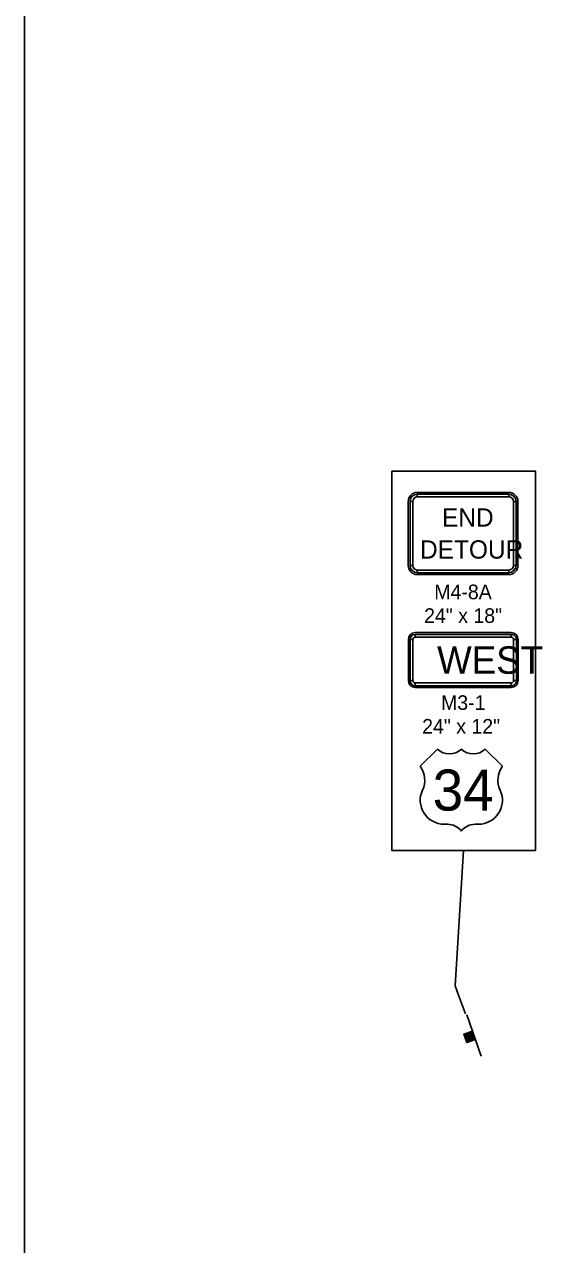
# Model space of a CAD drawing. Extents: x 10133 to 81668, y 6132 to 11018.
# Drawn here: x 10133 to 10418, y 8934 to 9603 of the extents above; entities that cross this region are included whole.
import ezdxf

# ---------------------------------------------------------------- set-up
doc = ezdxf.new("R2010")
doc.units = 0
for name, color, linetype in [('dsnTextFinalPlan', 7, 'Continuous'), ('Level 10', 7, 'Continuous'), ('Level 4', 7, 'Continuous'), ('Level 5', 7, 'Continuous'), ('SheetBorder', 7, 'Continuous'), ('SheetText', 7, 'Continuous')]:
    doc.layers.add(name, color=color, linetype=linetype)

msp = doc.modelspace()

# ---------------------------------------------------------------- linework, layer by layer
at = {"layer": 'dsnTextFinalPlan'}
for p, q in [((10374.94, 9060.01), (10382.82, 9037.34)), ((10373.66, 9049.53), (10375.26, 9044.93)), ((10375.52, 9045.02), (10373.92, 9049.62)), ((10374.11, 9049.69), (10375.71, 9045.08)), ((10375.97, 9045.17), (10374.37, 9049.78)), ((10374.56, 9049.84), (10376.14, 9045.23)), ((10376.5, 9045.36), (10374.91, 9049.97)), ((10375.08, 9050.03), (10376.68, 9045.42)), ((10377.04, 9045.54), (10375.44, 9050.15)), ((10375.75, 9050.26), (10377.35, 9045.65)), ((10377.61, 9045.74), (10376.02, 9050.35)), ((10376.19, 9050.41), (10377.8, 9045.81)), ((10378.01, 9045.88), (10376.41, 9050.49)), ((10376.69, 9050.58), (10378.29, 9045.98)), ((10378.46, 9046.04), (10376.86, 9050.64)), ((10377.04, 9050.71), (10378.65, 9046.1)), ((10378.86, 9046.18), (10377.26, 9050.78)), ((10377.48, 9050.86), (10379.08, 9046.25)), ((10379.31, 9046.33), (10377.71, 9050.94))]:
    msp.add_line(p, q, dxfattribs=at)
for points in [[(10333.75, 9358.04), (10412.57, 9358.04), (10412.57, 9150.14), (10333.75, 9150.14)], [(10333.75, 9358.04), (10412.57, 9358.04), (10412.57, 9150.14), (10333.75, 9150.14)], [(10379.57, 9046.42), (10377.96, 9051.06), (10373.32, 9049.45), (10374.94, 9044.81)]]:
    msp.add_lwpolyline(points, close=True, dxfattribs=at)
msp.add_lwpolyline([(10374.15, 9060.58), (10370.43, 9070.84), (10368.58, 9075.97), (10373.16, 9150.14)], dxfattribs=at)
at = {"layer": 'Level 10'}
for p, q in [((10342.78, 9341.49), (10342.78, 9306.42)), ((10343.78, 9341.49), (10343.78, 9306.42)), ((10345.29, 9341.49), (10343.78, 9341.49)), ((10343.78, 9341.49), (10345.29, 9341.49)), ((10345.29, 9306.42), (10345.29, 9341.49)), ((10397.9, 9346.5), (10347.79, 9346.5)), ((10347.79, 9344), (10347.79, 9345.5)), ((10397.9, 9345.5), (10347.79, 9345.5)), ((10347.79, 9345.5), (10347.79, 9344)), ((10347.79, 9344), (10397.9, 9344)), ((10397.9, 9344), (10397.9, 9345.5)), ((10397.9, 9345.5), (10397.9, 9344)), ((10400.4, 9341.49), (10401.91, 9341.49)), ((10400.4, 9341.49), (10400.4, 9306.42)), ((10401.91, 9341.49), (10400.4, 9341.49)), ((10401.91, 9306.42), (10401.91, 9341.49)), ((10402.91, 9306.42), (10402.91, 9341.49)), ((10343.78, 9306.42), (10345.29, 9306.42)), ((10345.29, 9306.42), (10343.78, 9306.42)), ((10397.9, 9303.91), (10347.79, 9303.91)), ((10347.79, 9303.91), (10347.79, 9302.41)), ((10347.79, 9302.41), (10347.79, 9303.91)), ((10347.79, 9302.41), (10397.9, 9302.41)), ((10347.79, 9301.41), (10397.9, 9301.41)), ((10397.9, 9303.91), (10397.9, 9302.41)), ((10397.9, 9302.41), (10397.9, 9303.91)), ((10400.4, 9306.42), (10401.91, 9306.42)), ((10401.91, 9306.42), (10400.4, 9306.42)), ((10346.65, 9269.57), (10399.26, 9269.57)), ((10346.65, 9267.07), (10346.65, 9268.63)), ((10399.26, 9268.63), (10399.26, 9267.07)), ((10342.89, 9243.26), (10342.89, 9265.81)), ((10343.83, 9265.81), (10345.39, 9265.81)), ((10400.51, 9265.81), (10402.08, 9265.81)), ((10403.02, 9265.81), (10403.02, 9243.26)), ((10345.39, 9243.26), (10343.83, 9243.26)), ((10346.65, 9240.45), (10346.65, 9242.01)), ((10399.26, 9242.01), (10399.26, 9240.45)), ((10402.08, 9243.26), (10400.51, 9243.26)), ((10399.26, 9239.51), (10346.65, 9239.51))]:
    msp.add_line(p, q, dxfattribs=at)
for points in [[(10399.26, 9268.63), (10346.65, 9268.63), (10346.65, 9267.07), (10399.26, 9267.07), (10399.26, 9268.63)], [(10343.83, 9265.81), (10343.83, 9243.26), (10345.39, 9243.26), (10345.39, 9265.81), (10343.83, 9265.81)], [(10402.08, 9243.26), (10402.08, 9265.81), (10400.51, 9265.81), (10400.51, 9243.26), (10402.08, 9243.26)], [(10346.65, 9240.45), (10399.26, 9240.45), (10399.26, 9242.01), (10346.65, 9242.01), (10346.65, 9240.45)]]:
    msp.add_lwpolyline(points, close=True, dxfattribs=at)
for centre, radius, start, end in [((10347.79, 9341.49), 5.01, 90, 180), ((10347.79, 9341.49), 4.01, 90, 180), ((10347.79, 9341.49), 2.51, 90, 180), ((10397.9, 9341.49), 5.01, 0, 90), ((10397.9, 9341.49), 4.01, 0, 90), ((10397.9, 9341.49), 2.51, 0, 90), ((10347.79, 9306.42), 5.01, 180, 270), ((10347.79, 9306.42), 4.01, 180, 270), ((10347.79, 9306.42), 2.51, 180, 270), ((10397.9, 9306.42), 2.51, 270, 0), ((10397.9, 9306.42), 4.01, 270, 360), ((10397.9, 9306.42), 5.01, 270, 0), ((10346.65, 9265.81), 3.76, 90, 180), ((10346.65, 9265.81), 2.82, 90.00021, 179.99985), ((10346.65, 9265.81), 1.25, 90.00021, 179.99985), ((10399.26, 9265.81), 3.76, 0, 90), ((10399.26, 9265.81), 2.82, 0, 90.00021), ((10399.26, 9265.81), 1.25, 0, 90.00021), ((10346.65, 9243.26), 3.76, 180, 270), ((10346.65, 9243.26), 2.82, 179.99985, 270.00006), ((10346.65, 9243.26), 1.25, 179.99985, 270.00006), ((10399.26, 9243.26), 2.82, 270.00006, 0.00027), ((10399.26, 9243.26), 1.25, 270.00006, 0.00027), ((10399.26, 9243.26), 3.76, 270, 359.99112)]:
    msp.add_arc(centre, radius, start, end, dxfattribs=at)
at = {"layer": 'Level 4'}
for p, q in [((10358.78, 9205.75), (10349.4, 9196.37)), ((10358.78, 9205.75), (10349.4, 9196.37)), ((10358.78, 9205.75), (10349.4, 9196.37)), ((10394.4, 9196.37), (10385.03, 9205.75)), ((10394.4, 9196.37), (10385.03, 9205.75)), ((10394.4, 9196.37), (10385.03, 9205.75)), ((10362.53, 9164.5), (10364.4, 9164.5)), ((10362.53, 9164.5), (10364.4, 9164.5)), ((10362.53, 9164.5), (10364.4, 9164.5)), ((10379.4, 9164.5), (10381.28, 9164.5)), ((10379.4, 9164.5), (10381.28, 9164.5)), ((10379.4, 9164.5), (10381.28, 9164.5))]:
    msp.add_line(p, q, dxfattribs=at)
for centre, radius, start, end in [((10365.34, 9212.44), 9.38, 225.57291, 314.42721), ((10365.34, 9212.44), 9.38, 225.57291, 314.42721), ((10365.34, 9212.44), 9.38, 225.57291, 314.42721), ((10378.46, 9212.44), 9.38, 225.57291, 314.42721), ((10378.46, 9212.44), 9.38, 225.57291, 314.42721), ((10378.46, 9212.44), 9.38, 225.57291, 314.42721), ((10338.74, 9188.72), 13.13, 334.98952, 35.66288), ((10338.74, 9188.72), 13.13, 334.98952, 35.66288), ((10338.74, 9188.72), 13.13, 334.98952, 35.66288), ((10405.07, 9188.72), 13.13, 144.33724, 205.01003), ((10405.07, 9188.72), 13.13, 144.33724, 205.01003), ((10405.07, 9188.72), 13.13, 144.33724, 205.01003), ((10362.53, 9177.62), 13.13, 154.98967, 270.00006), ((10362.53, 9177.62), 13.13, 154.98967, 270.00006), ((10362.53, 9177.62), 13.13, 154.98967, 270.00006), ((10381.28, 9177.62), 13.13, 270.00006, 25.01045), ((10381.28, 9177.62), 13.13, 270.00006, 25.01045), ((10381.28, 9177.62), 13.13, 270.00006, 25.01045), ((10364.4, 9155.12), 9.38, 36.86989, 90.00021), ((10364.4, 9155.12), 9.38, 36.86989, 90.00021), ((10364.4, 9155.12), 9.38, 36.86989, 90.00021), ((10379.4, 9155.12), 9.38, 90.00021, 143.13001), ((10379.4, 9155.12), 9.38, 90.00021, 143.13001), ((10379.4, 9155.12), 9.38, 90.00021, 143.13001)]:
    msp.add_arc(centre, radius, start, end, dxfattribs=at)
at = {"layer": 'SheetBorder'}
msp.add_lwpolyline([(10132.52, 9944.02), (13267.53, 9944.02), (13267.53, 7924.02), (10132.52, 7924.02)], close=True, dxfattribs=at)
at = {"layer": 'SheetText'}
msp.add_lwpolyline([(10132.52, 9944.02), (10132.52, 7924.02), (13267.53, 7924.02), (13267.53, 9944.02)], close=True, dxfattribs=at)

# ---------------------------------------------------------------- texts
at = {"layer": 'Level 10'}
for s, height, p in [('END', 10.021, (10361.32, 9327.71)), ('DETOUR', 10.021, (10349.27, 9310.17)), ('WEST', 15.032, (10358.62, 9247.02))]:
    msp.add_text(s, height=height, dxfattribs=at).set_placement(p)
at = {"layer": 'Level 4'}
msp.add_text('34', height=22.5, dxfattribs=at).set_placement((10356.2, 9172))
msp.add_text('34', height=22.5, dxfattribs=at).set_placement((10356.2, 9172))
msp.add_text('34', height=22.5, dxfattribs=at).set_placement((10356.2, 9172))
at = {"layer": 'Level 5'}
for s, p in [('M4-8A', (10357.07, 9287.92)), ('24" x 18"', (10351.51, 9274.92)), ('M3-1', (10360.77, 9227.21)), ('24" x 12"', (10350.44, 9214.21))]:
    msp.add_text(s, height=8, dxfattribs=at).set_placement(p)

doc.saveas('drawing.dxf')
